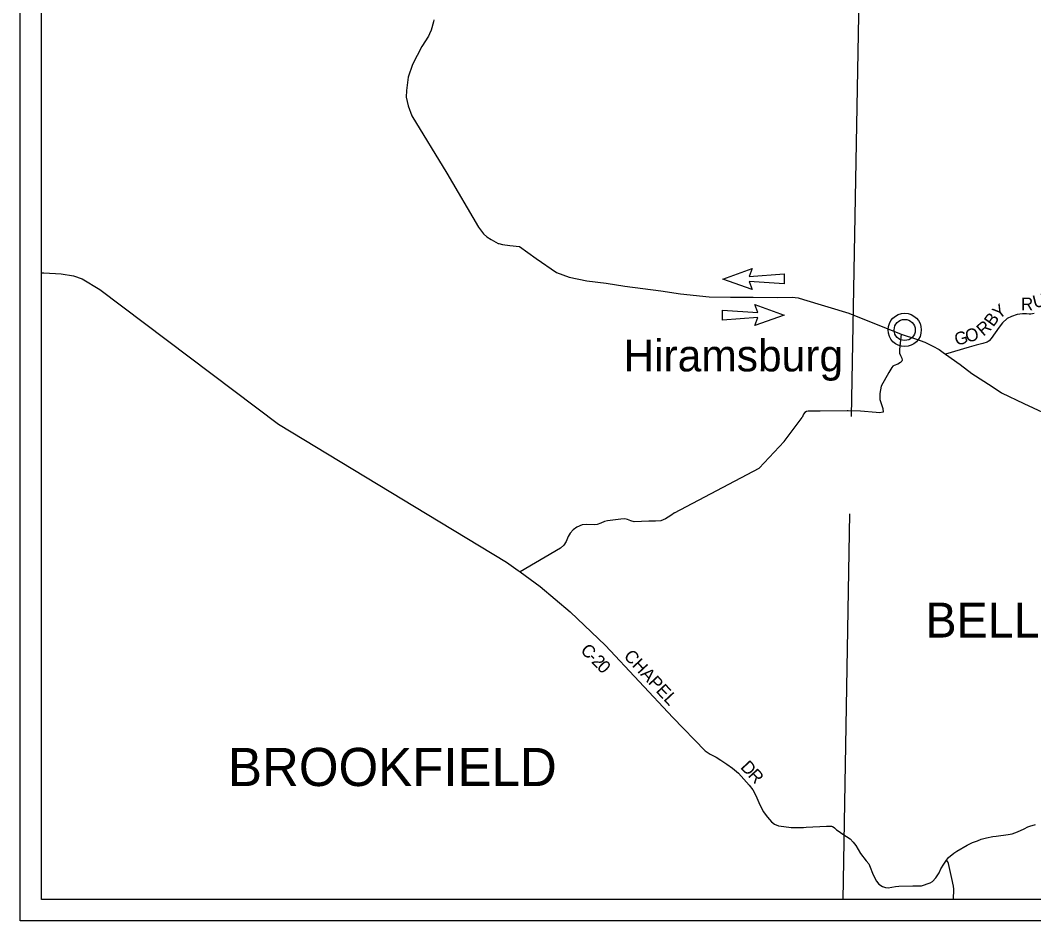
# Model space of a CAD drawing. Extents: x 0 to 34, y 0 to 22.
# Drawn here: x 19.758 to 24.277, y 9.524 to 13.537 of the extents above; entities that cross this region are included whole.
import ezdxf

# ---------------------------------------------------------------- set-up
doc = ezdxf.new("R2010")
doc.units = 0
for name, color, linetype in [('Default', 7, 'Continuous'), ('GM_X_County_Road_Text', 7, 'Continuous'), ('GM_X_Township', 7, 'Continuous'), ('GM_X_Township_Text', 7, 'Continuous'), ('GM_X_Unincorporated', 7, 'Continuous'), ('GM_X_Unincorporated_Text', 7, 'Continuous')]:
    doc.layers.add(name, color=color, linetype=linetype)

msp = doc.modelspace()

# ---------------------------------------------------------------- linework, layer by layer
at = {"layer": 'Default'}
for p, q in [((19.8526, 9.6182), (19.8526, 20.4625)), ((22.8905, 12.3841), (23.0214, 12.4311)), ((23.0214, 12.4311), (23.0077, 12.3955)), ((23.0214, 12.3372), (22.8905, 12.3841)), ((23.0077, 12.3955), (23.1649, 12.4066)), ((23.1649, 12.4066), (23.1648, 12.3619)), ((23.1648, 12.3619), (23.0077, 12.373)), ((23.0077, 12.373), (23.0214, 12.3372)), ((23.0469, 12.2345), (23.0332, 12.27)), ((23.0332, 12.27), (23.164, 12.2232)), ((22.8897, 12.2007), (22.8897, 12.2456)), ((22.8897, 12.2456), (23.0469, 12.2345)), ((23.0468, 12.2118), (22.8897, 12.2007)), ((23.164, 12.2232), (23.0331, 12.1762)), ((23.0331, 12.1762), (23.0468, 12.2118)), ((30.697, 9.6182), (19.8526, 9.6182))]:
    msp.add_line(p, q, dxfattribs=at)
msp.add_lwpolyline([(19.7581, 20.557), (30.7915, 20.557), (30.7915, 9.5237), (19.7581, 9.5237)], close=True, dxfattribs=at)
for points in [[(21.6018, 13.5388), (21.601, 13.5305), (21.5898, 13.4932), (21.5826, 13.4763), (21.5785, 13.4668), (21.5487, 13.4207), (21.5071, 13.3406), (21.4873, 13.2837), (21.4808, 13.225), (21.4789, 13.1948), (21.4881, 13.1564), (21.5045, 13.1111), (21.6601, 12.8552), (21.8012, 12.6153), (21.8231, 12.5847), (21.839, 12.5722), (21.8575, 12.5604), (21.8891, 12.5425), (21.8926, 12.5423), (21.9081, 12.5378), (21.9408, 12.5337), (21.9839, 12.5288), (22.0582, 12.4757), (22.149, 12.4124), (22.2051, 12.3926), (22.2851, 12.3763), (22.3703, 12.3653), (22.4533, 12.3517), (22.6143, 12.3316), (22.7018, 12.318), (22.8302, 12.305), (22.9256, 12.3032), (23.026, 12.3037), (23.1324, 12.3019), (23.1998, 12.3026), (23.2271, 12.2997), (23.2506, 12.2926), (23.4531, 12.2311), (23.6855, 12.1388), (23.7541, 12.1154), (23.792, 12.1027), (23.8277, 12.0854), (23.8561, 12.0704), (23.8789, 12.0519), (23.8831, 12.0489), (23.9492, 12.0026), (24.0012, 11.963), (24.0911, 11.9047), (24.1333, 11.8761), (24.2331, 11.8296), (24.3806, 11.7602)], [(19.8526, 12.412), (19.863, 12.4121), (19.94, 12.4065), (19.9948, 12.3986), (20.0341, 12.385), (20.1135, 12.3367), (20.909, 11.7366), (21.6286, 11.3017), (21.9266, 11.1217), (21.9787, 11.0844)], [(24.2786, 12.2299), (24.2711, 12.2287), (24.2636, 12.227), (24.2564, 12.2272), (24.245, 12.2289), (24.2276, 12.2294), (24.2027, 12.2255), (24.1776, 12.2167), (24.1588, 12.2077), (24.1372, 12.188), (24.1236, 12.1699), (24.087, 12.1189), (24.0777, 12.1089), (24.0688, 12.103), (24.0496, 12.0966), (24.0199, 12.0893), (23.9886, 12.0804), (23.8831, 12.0489)], [(23.6855, 12.1388), (23.6806, 12.0854), (23.6784, 12.0684), (23.678, 12.0586), (23.6784, 12.0529), (23.6826, 12.0438), (23.689, 12.0317), (23.6909, 12.023), (23.689, 12.0177), (23.6837, 12.0116), (23.6717, 12.0048), (23.6547, 11.9983), (23.6486, 11.9949), (23.6437, 11.9892), (23.6305, 11.968), (23.5965, 11.9064), (23.5909, 11.8737), (23.5913, 11.8466), (23.6048, 11.8064), (23.6061, 11.7909), (23.5901, 11.788), (23.5745, 11.7896), (23.5048, 11.795), (23.4499, 11.7965), (23.4459, 11.7964)], [(23.4459, 11.7964), (23.3242, 11.7949), (23.2713, 11.7955), (23.2634, 11.7936), (23.2558, 11.7891), (23.2501, 11.7819), (23.2441, 11.7665)], [(22.6752, 11.3425), (22.8639, 11.4419), (23.0526, 11.5413), (23.1643, 11.6602), (23.2441, 11.7665)], [(22.6752, 11.3425), (22.6584, 11.3301), (22.635, 11.3157), (22.6138, 11.3066), (22.59, 11.3043), (22.5613, 11.3042), (22.4952, 11.3022), (22.4808, 11.306), (22.4657, 11.3128), (22.454, 11.3154), (22.4359, 11.3135), (22.3769, 11.3066), (22.3633, 11.3028), (22.3463, 11.296), (22.3308, 11.2903), (22.3169, 11.288), (22.2851, 11.2891), (22.2643, 11.2879), (22.2398, 11.2773), (22.2228, 11.2655), (22.21, 11.2507), (22.2017, 11.2359), (22.1922, 11.214), (22.1817, 11.1977), (22.1666, 11.1844), (21.9873, 11.0781)], [(21.9787, 11.0844), (21.9787, 11.0844), (21.9873, 11.0781), (22.0768, 11.014), (22.2101, 10.9007), (22.3679, 10.7505), (22.6682, 10.4294), (22.8123, 10.2805), (22.8339, 10.2665), (22.8618, 10.2525), (22.8826, 10.2393), (22.9091, 10.2212), (22.9337, 10.2042), (22.9601, 10.1808), (23.0086, 10.1282), (23.0244, 10.1067), (23.0377, 10.0825), (23.0513, 10.0511), (23.0702, 10.0103), (23.0899, 9.9849), (23.1077, 9.9649), (23.1205, 9.9547), (23.1383, 9.9468), (23.1633, 9.9434), (23.195, 9.9385), (23.2509, 9.9394), (23.2622, 9.94)], [(23.2622, 9.94), (23.3529, 9.9448), (23.3749, 9.9445), (23.3799, 9.944), (23.3873, 9.9385), (23.3879, 9.9379)], [(23.8878, 9.7939), (23.8972, 9.8049), (23.9206, 9.8242), (23.9338, 9.8341), (23.9803, 9.8602), (24.0044, 9.872), (24.026, 9.8804), (24.043, 9.8868), (24.0672, 9.8937), (24.0951, 9.899), (24.1102, 9.9005), (24.1628, 9.9074), (24.1809, 9.9113), (24.2047, 9.9192), (24.2338, 9.9337), (24.2515, 9.9424), (24.2598, 9.9454), (24.2855, 9.9527)], [(23.3879, 9.9379), (23.3886, 9.9371), (23.3972, 9.9282), (23.4051, 9.9239), (23.4258, 9.91), (23.4587, 9.8893), (23.4719, 9.8733), (23.4838, 9.8587), (23.5046, 9.8236), (23.5292, 9.7899), (23.5416, 9.7767), (23.5447, 9.7703), (23.5617, 9.7279), (23.5753, 9.6996), (23.5859, 9.6867), (23.6029, 9.6765), (23.6165, 9.672), (23.6283, 9.6709), (23.6445, 9.6728), (23.66, 9.6762), (23.6762, 9.6781), (23.7375, 9.6786), (23.7768, 9.6798), (23.8149, 9.6927), (23.8251, 9.6984), (23.8413, 9.7143), (23.8549, 9.7371), (23.8632, 9.7556), (23.8757, 9.7753), (23.8878, 9.7939)], [(23.9198, 9.6182), (23.9207, 9.6641), (23.9192, 9.677), (23.9124, 9.7118), (23.8976, 9.7788), (23.8938, 9.7859), (23.8878, 9.7939)]]:
    msp.add_lwpolyline(points, dxfattribs=at)
at = {"layer": 'GM_X_Township'}
for p, q in [((23.5089, 14.3112), (23.4636, 11.7712)), ((23.4559, 11.3376), (23.4253, 9.6182))]:
    msp.add_line(p, q, dxfattribs=at)
at = {"layer": 'GM_X_Unincorporated'}
for radius in [0.0742, 0.0471]:
    msp.add_circle((23.7017, 12.157), radius, dxfattribs=at)

# ---------------------------------------------------------------- texts
at = {"layer": 'GM_X_County_Road_Text'}
for s, rotation, p in [('R', 0.1836, (24.22, 12.2446)), ('U', 14.0943, (24.2807, 12.2529)), ('Y', 37.7945, (24.1211, 12.202)), ('B', 54.1603, (24.0968, 12.1674)), ('O', 16.0094, (23.9807, 12.0996)), ('R', 41.3104, (24.0525, 12.1264)), ('G', 15.9564, (23.9327, 12.0859)), ('C', 315.8418, (22.2525, 10.7245)), ('CHAPEL', 312.9989, (22.4457, 10.7004)), ('-', 314.9117, (22.2857, 10.6923)), ('2', 314.2567, (22.3021, 10.6759)), ('0', 313.7672, (22.3264, 10.651)), ('D', 313.0162, (22.9662, 10.2056)), ('R', 312.2225, (23.0001, 10.1693))]:
    msp.add_text(s, height=0.0567, rotation=rotation, dxfattribs=at).set_placement(p)
at = {"layer": 'GM_X_Township_Text'}
msp.add_text('BROOKFIELD', height=0.1701, rotation=0, dxfattribs=at).set_placement((20.6843, 10.124))
at = {"layer": 'GM_X_Unincorporated_Text'}
for s, height, p in [('Hiramsburg', 0.14175, (22.4474, 11.9724)), ('BELLE VALLEY', 0.155676, (23.7942, 10.7858))]:
    msp.add_text(s, height=height, rotation=0, dxfattribs=at).set_placement(p)

doc.saveas('drawing.dxf')
